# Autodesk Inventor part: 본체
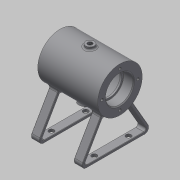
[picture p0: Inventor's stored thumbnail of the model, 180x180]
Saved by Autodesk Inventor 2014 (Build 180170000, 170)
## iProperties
Created: 2016-03
Part Number: 본체
Material: 일반
Document SubType Name: Modeling
Designer: SCD-A15
Density: 1 g/cm^3
Appearance: 기본값
Author: SCD-A15
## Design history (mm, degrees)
sketch "스케치2"
  geometry: L1 (0, 0)-(70, 0); L2 (0, 0)-(0, 26); L3 (0, 26)-(70, 26); L4 (70, 26)-(70, 0); L5 (0, 16)-(12, 16); L6 (12, 16)-(12, 14); L7 (12, 14)-(14, 14); L8 (14, 14)-(14, 21); L9 (14, 21)-(56, 21); L10 (56, 21)-(56, 14); L11 (56, 14)-(58, 14); L12 (58, 14)-(58, 16); L13 (58, 16)-(70, 16)
  constraints: 26 end point, 7 parallel, 5 perpendicular, 2 point on line, 1 horizontal
  dimensions: "d0" = 70 distance of L1.start L1.end; "d1" = 32 diameter of L5.start L1; "d2" = 28 diameter of L6.end L1; "d3" = 52 diameter of L2.end L1; "d4" = 42 diameter of L8.end L1; "d5" = 28 diameter of L11.end L1; "d6" = 32 diameter of L12.end L1; "d7" = 12 distance of L5.start L5.end; "d8" = 42 distance of L8.end L9.end; "d9" = 12 distance of L12.end L13.end; "d10" = 2 distance of L6.end L7.end
revolve "회전1" sketch "스케치2" stored, may be unused: angle "d11" = 90 deg
node "작업 평면2"
  node "작업 평면1"
sketch "스케치3"
  geometry: L1 (35, 26)-(35, -26) reference; L2 (-35, 26)-(-35, -26) reference; L3 (35, -26)-(-35, -26) reference; C1 r 5 at (0, 0); 2 further points
  constraints: 1 centre point, 1 horizontal alignment, 1 midpoint, 1 vertical alignment
  dimensions: "d13" = 10 diameter of C1
extrude "돌출1" join sketch "스케치3" stored distance "d14" = 10; taper "d15" = 0 deg
node "작업 평면4"
  node "작업 평면3"
sketch "스케치4"
  geometry: L1 (-42.594, -65)-(42.594, -65); L2 (0, 0)-(0, -65); L3 (-42.594, -65)-(-16.613, -20); L4 (-16.613, -20)-(-14.015, -21.5); L5 (-14.015, -21.5)-(-37.398, -62); L6 (-37.398, -62)-(37.398, -62); L7 (37.398, -62)-(14.015, -21.5); L8 (14.015, -21.5)-(16.613, -20); L9 (16.613, -20)-(42.594, -65); 2 further points
  constraints: 18 end point, 4 perpendicular, 2 midpoint, 2 parallel, 1 horizontal, 1 vertical alignment, 2 other
  dimensions: "d17" = 65 distance from line of L1 point (0, 0); "d18" = 3 distance between parallel lines of L6 L1; "d19" = 3 distance between parallel lines of L5 L3; "d20" = 3 distance between parallel lines of L9 L7; "d21" = 30 deg angle of L3 L2; "d22" = 30 deg angle of L9 L2; "d23" = 45 distance from line of L8.end L1; "d24" = 45 distance from line of L3.end L1
extrude "돌출2" join sketch "스케치4" distance "d27" = 10; taper "d28" = 0 deg
node "작업 평면10"
sketch "스케치6"
  geometry: L1 (0, 0)-(7.506, -28.012); L2 (0, 0)-(0, -37.231); L3 (7.506, -28.012)-(5.796, -21.629); L4 (5.796, -21.629)-(0, -23.182); L5 (0, -23.182)-(1.71, -29.565); L6 (1.71, -29.565)-(7.506, -28.012); C1 r 26 at (0, 0) reference; 1 further point
  constraints: 12 end point, 2 parallel, 2 point on line, 1 perpendicular, 1 vertical
  dimensions: "d35" = 15 deg angle of L1 L2; "d36" = 29 distance of L1.end point (0, 0); "d37" = 6 distance between parallel lines of L3 L5
revolve "회전2" sketch "스케치6" stored, may be unused: angle "d38" = 90 deg
sketch "스케치7" dims "d39" = 42
  geometry: C1 r 16 at (0, 0) reference; C2 r 26 at (0, 0) reference; 2 further points
  constraints: 2 vertical alignment, 1 coincident, 2 other
hole "구멍1" sketch "스케치7" at (0, 21) diameter "d40" = 3.242; stored, may be unused: countersink angle "d44" = 90 deg, drill point angle "d46" = 118 deg; dims "d41" = 8, "d42" = 4, "d43" = 2, "d45" = 10
hole "구멍2" diameter "d52" = 5.188; stored, may be unused: countersink angle "d56" = 90 deg, drill point angle "d58" = 118 deg; dims "d50" = 10, "d51" = 10, "d53" = 8, "d54" = 4, "d55" = 2, "d57" = 10
hole "구멍3" diameter "d61" = 5.188; stored, may be unused: countersink angle "d65" = 90 deg, drill point angle "d67" = 118 deg; dims "d59" = 10, "d60" = 10, "d62" = 8, "d63" = 4, "d64" = 2, "d66" = 10
fillet "모깎기2" dims "d73" = 0.3
fillet "모깎기3" dims "d74" = 3
fillet "모깎기4" dims "d75" = 2
fillet "모깎기5" dims "d76" = 2
fillet "모깎기6" dims "d77" = 5
fillet "모깎기7" dims "d78" = 2.5
chamfer "모따기1" distance "d79" = 1; stored, may be unused: second distance "d80" = 2, angle "d81" = 45 deg
fillet "모깎기8" dims "d82" = 3
fillet "모깎기9" dims "d83" = 0.5
fillet "모깎기10" dims "d84" = 3
fillet "모깎기11" dims "d88" = 0.5
sketch "스케치9"
  geometry: L1 (0, 66.135)-(9, 66.135) reference; L2 (9, 0)-(0, 0) reference; L3 (4.5, 66.135)-(4.5, 0); C1 r 3 at (4.5, 53.068); C2 r 3 at (4.5, 13.068); 1 further point
  constraints: 2 centre point, 2 end point, 2 midpoint, 2 point on line, 1 equal radius
  dimensions: "d89" = 40 distance of C2.centre C1.centre; "d90" = 20 vertical distance of point (-5.5, 33.068) C1.centre; "d91" = 6 diameter of C1
extrude "돌출4" cut sketch "스케치9" stored distance "d92" = 10; taper "d93" = 0 deg
node "작업 평면12"
  node "작업 평면11"
sketch "스케치10"
  geometry: L1 (35, 26)-(-35, 26) reference; 3 further points
  constraints: 1 horizontal alignment, 1 midpoint, 1 vertical alignment, 1 other
feature "엠보싱1" sketch "스케치10" dims "d95" = 0.5, "d96" = 0
node "솔리드1"
mirror "대칭1"
pattern_circular "원형 패턴1" dims angle "d48" = 360 deg
mirror "대칭2"
mirror "대칭4"
node "투영된 루프1"
other parameters: "d12" = 3, "d94" = 90 deg
